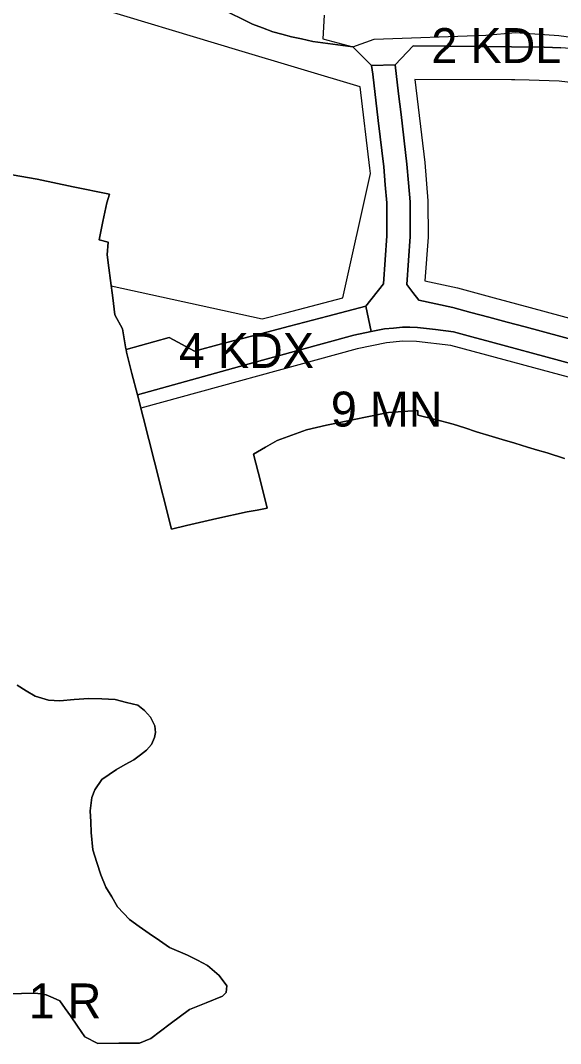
# Model space of a CAD drawing. Extents: x 7422252 to 7424226, y 5538569 to 5540380.
# Drawn here: x 7423241.3 to 7423473.1, y 5539105.5 to 5539544.8 of the extents above; entities that cross this region are included whole.
import ezdxf

# ---------------------------------------------------------------- set-up
doc = ezdxf.new("R2010")
doc.units = 0
for name, color, linetype in [('linie_rozgraniczajace', 7, 'Continuous'), ('linie_zabudowy_nieprzekraczalne', 7, 'Continuous'), ('oznaczenia_przeznaczen', 7, 'Continuous')]:
    doc.layers.add(name, color=color, linetype=linetype)

msp = doc.modelspace()

# ---------------------------------------------------------------- linework, layer by layer
at = {"layer": 'linie_rozgraniczajace'}
for points in [[(7423327.05, 5539549.99), (7423340.85, 5539543.2), (7423345.26, 5539541.53), (7423349.67, 5539539.85), (7423353.43, 5539538.87), (7423357.61, 5539537.79), (7423362, 5539536.8), (7423366.79, 5539535.72), (7423375.39, 5539534.56), (7423383.98, 5539533.39), (7423392.01, 5539525.41), (7423392.53, 5539521.74), (7423394.89, 5539501.82), (7423397.25, 5539481.91), (7423397.88, 5539474.2), (7423398.51, 5539466.5), (7423398.55, 5539459.42), (7423398.6, 5539452.35), (7423397.86, 5539442), (7423397.12, 5539431.65), (7423389.6, 5539422.06), (7423373.16, 5539417.77), (7423356.72, 5539413.47), (7423342.12, 5539409.7), (7423327.53, 5539405.92), (7423316.06, 5539402.76), (7423305.1, 5539408.56), (7423286.64, 5539403.47), (7423286.58, 5539403.78), (7423285.85, 5539408.09), (7423285.11, 5539412.39), (7423281.84, 5539418.31), (7423280.9, 5539425.68), (7423279.95, 5539433.06), (7423279.25, 5539438.59), (7423278.54, 5539444.13), (7423278.91, 5539449.5), (7423275.05, 5539450.54), (7423276.69, 5539458.48), (7423278.33, 5539466.42), (7423279.5, 5539470.1), (7423263.98, 5539473.36), (7423248.47, 5539476.61), (7423237.81, 5539478.49)], [(7423371.61, 5539547.02), (7423371.09, 5539536.9), (7423383.98, 5539533.39), (7423375.39, 5539534.56), (7423366.79, 5539535.72), (7423362, 5539536.8), (7423357.61, 5539537.79), (7423353.43, 5539538.87), (7423349.67, 5539539.85), (7423345.26, 5539541.53), (7423340.85, 5539543.2), (7423327.05, 5539549.99)], [(7423402.14, 5539525.64), (7423409.89, 5539533.83), (7423438.01, 5539533.58), (7423466.12, 5539533.33), (7423473.15, 5539533.05)], [(7423389.6, 5539422.06), (7423397.12, 5539431.65), (7423397.86, 5539442), (7423398.6, 5539452.35), (7423398.55, 5539459.42), (7423398.51, 5539466.5), (7423397.88, 5539474.2), (7423397.25, 5539481.91), (7423394.89, 5539501.82), (7423392.53, 5539521.74), (7423392.01, 5539525.41), (7423402.14, 5539525.64), (7423403.61, 5539513.23), (7423404.66, 5539504.35), (7423407.19, 5539483.06), (7423407.85, 5539475), (7423408.51, 5539466.94), (7423408.55, 5539459.48), (7423408.6, 5539452.02), (7423407.86, 5539441.69), (7423407.12, 5539431.37), (7423409.7, 5539428.01), (7423412.27, 5539424.65), (7423419.55, 5539423.08), (7423426.83, 5539421.5), (7423434.6, 5539419.41), (7423442.37, 5539417.32), (7423450.13, 5539415.23), (7423457.88, 5539413.14), (7423481.67, 5539406.73)], [(7423481.67, 5539406.73), (7423457.88, 5539413.14), (7423450.13, 5539415.23), (7423442.37, 5539417.32), (7423434.6, 5539419.41), (7423426.83, 5539421.5), (7423419.55, 5539423.08), (7423412.27, 5539424.65), (7423409.7, 5539428.01), (7423407.12, 5539431.37), (7423407.86, 5539441.69), (7423408.6, 5539452.02), (7423408.55, 5539459.48), (7423408.51, 5539466.94), (7423407.85, 5539475), (7423407.19, 5539483.06), (7423404.66, 5539504.35), (7423403.61, 5539513.23), (7423402.14, 5539525.64)], [(7423237.81, 5539478.49), (7423248.47, 5539476.61), (7423263.98, 5539473.36), (7423279.5, 5539470.1), (7423278.33, 5539466.42), (7423276.69, 5539458.48), (7423275.05, 5539450.54), (7423278.91, 5539449.5), (7423278.54, 5539444.13), (7423279.25, 5539438.59), (7423279.95, 5539433.06), (7423280.9, 5539425.68), (7423281.84, 5539418.31), (7423285.11, 5539412.39), (7423285.85, 5539408.09), (7423286.58, 5539403.78), (7423286.64, 5539403.47), (7423286.82, 5539402.39), (7423289.15, 5539393.22), (7423291.49, 5539384.06), (7423298.83, 5539355.2), (7423306.18, 5539326.34), (7423312.56, 5539327.92), (7423325.58, 5539330.87), (7423338.59, 5539333.83), (7423342.9, 5539334.56), (7423347.21, 5539335.3), (7423344.3, 5539346.93), (7423341.4, 5539358.56), (7423346.43, 5539361.48), (7423351.45, 5539364.4), (7423357.79, 5539366.71), (7423364.13, 5539369.02), (7423368.42, 5539369.99), (7423372.71, 5539370.95), (7423376.88, 5539371.8), (7423381.04, 5539372.65), (7423389.43, 5539374.36), (7423399.23, 5539376.36), (7423405.4, 5539376.82), (7423411.86, 5539377.31), (7423411.86, 5539375.24), (7423419.47, 5539373.36), (7423427.08, 5539371.47)], [(7423502.3, 5539390.81), (7423472.64, 5539398.81), (7423442.98, 5539406.8), (7423435.05, 5539408.93), (7423427.12, 5539411.07), (7423419.39, 5539412.01), (7423411.66, 5539412.95), (7423408.44, 5539413.03), (7423405.22, 5539413.1), (7423401.37, 5539412.69), (7423397.52, 5539412.29), (7423394.68, 5539411.72), (7423391.84, 5539411.15), (7423389.6, 5539422.06)], [(7423474.83, 5539356.61), (7423467.35, 5539359.07), (7423463.16, 5539360.32), (7423458.98, 5539361.57), (7423453.48, 5539363.22), (7423447.98, 5539364.86), (7423443.78, 5539366.12), (7423436.96, 5539368.16), (7423432.02, 5539369.81), (7423427.08, 5539371.47), (7423419.47, 5539373.36), (7423411.86, 5539375.24), (7423411.86, 5539377.31), (7423405.4, 5539376.82), (7423399.23, 5539376.36), (7423389.43, 5539374.36), (7423381.04, 5539372.65), (7423376.88, 5539371.8), (7423372.71, 5539370.95), (7423368.42, 5539369.99), (7423364.13, 5539369.02), (7423357.79, 5539366.71), (7423351.45, 5539364.4), (7423346.43, 5539361.48), (7423341.4, 5539358.56), (7423344.3, 5539346.93), (7423347.21, 5539335.3), (7423342.9, 5539334.56), (7423338.59, 5539333.83), (7423325.58, 5539330.87), (7423312.56, 5539327.92), (7423306.18, 5539326.34), (7423298.83, 5539355.2), (7423291.49, 5539384.06), (7423337.92, 5539396.85), (7423384.36, 5539409.65), (7423391.84, 5539411.15), (7423394.68, 5539411.72), (7423397.52, 5539412.29), (7423401.37, 5539412.69), (7423405.22, 5539413.1), (7423408.44, 5539413.03), (7423411.66, 5539412.95), (7423419.39, 5539412.01), (7423427.12, 5539411.07), (7423435.05, 5539408.93), (7423442.98, 5539406.8), (7423472.64, 5539398.81), (7423502.3, 5539390.81)], [(7423427.08, 5539371.47), (7423432.02, 5539369.81), (7423436.96, 5539368.16), (7423443.78, 5539366.12), (7423447.98, 5539364.86), (7423453.48, 5539363.22), (7423458.98, 5539361.57), (7423463.16, 5539360.32), (7423467.35, 5539359.07), (7423474.83, 5539356.61)], [(7423239.86, 5539259.34), (7423243.77, 5539256.98), (7423247.69, 5539254.62), (7423250.56, 5539253.75), (7423253.43, 5539252.89), (7423255.8, 5539252.8), (7423258.18, 5539252.7), (7423264.42, 5539253.19), (7423270.66, 5539253.68), (7423276.31, 5539253.42), (7423281.96, 5539253.16), (7423286.81, 5539251.97), (7423291.67, 5539250.78), (7423294.59, 5539248.47), (7423297.09, 5539245.58), (7423297.77, 5539244.44), (7423299, 5539241.83), (7423299.21, 5539238.97), (7423298.89, 5539236.94), (7423297.53, 5539233.93), (7423295.38, 5539231.43), (7423292.83, 5539229.39), (7423289.92, 5539227.29), (7423286.23, 5539225.23), (7423282.55, 5539223.18), (7423276.28, 5539218.84), (7423273.2, 5539214.47), (7423271.95, 5539211.09), (7423271.28, 5539205.34), (7423271.47, 5539200.71), (7423271.66, 5539196.08), (7423272.44, 5539188.6), (7423274.15, 5539183.27), (7423275.86, 5539177.94), (7423277.96, 5539172.64), (7423280.5, 5539168.42), (7423283.04, 5539164.21), (7423285.56, 5539161.45), (7423288.08, 5539158.68), (7423292.33, 5539155.73), (7423296.58, 5539152.77), (7423300.96, 5539149.77), (7423305.35, 5539146.77), (7423312.98, 5539143.38), (7423317.29, 5539141.22), (7423321.6, 5539139.06), (7423326.67, 5539134.73), (7423329.86, 5539130.23), (7423329.6, 5539127.45), (7423328.01, 5539125.86), (7423320.98, 5539122.99), (7423313.94, 5539120.12), (7423305.64, 5539113.91), (7423297.33, 5539107.69), (7423292.42, 5539105.71), (7423283.49, 5539105.6), (7423274.56, 5539105.49), (7423268.9, 5539108.4), (7423265.83, 5539112.88), (7423262.76, 5539117.37), (7423260.48, 5539120.57), (7423258.2, 5539123.77), (7423255.31, 5539125.07), (7423252.42, 5539126.37), (7423250, 5539126.76), (7423247.59, 5539127.15), (7423241.8, 5539127.02), (7423236.02, 5539126.88)], [(7423271.95, 5539211.09), (7423273.2, 5539214.47), (7423276.28, 5539218.84), (7423282.55, 5539223.18), (7423286.23, 5539225.23), (7423289.92, 5539227.29), (7423292.83, 5539229.39), (7423295.38, 5539231.43), (7423297.53, 5539233.93), (7423298.89, 5539236.94), (7423299.21, 5539238.97), (7423299, 5539241.83), (7423297.77, 5539244.44), (7423297.09, 5539245.58), (7423294.59, 5539248.47), (7423291.67, 5539250.78), (7423286.81, 5539251.97), (7423281.96, 5539253.16), (7423276.31, 5539253.42), (7423270.66, 5539253.68), (7423264.42, 5539253.19), (7423258.18, 5539252.7), (7423255.8, 5539252.8), (7423253.43, 5539252.89), (7423250.56, 5539253.75), (7423247.69, 5539254.62), (7423243.77, 5539256.98), (7423239.86, 5539259.34)], [(7423236.02, 5539126.88), (7423241.8, 5539127.02), (7423247.59, 5539127.15), (7423250, 5539126.76), (7423252.42, 5539126.37), (7423255.31, 5539125.07), (7423258.2, 5539123.77), (7423260.48, 5539120.57), (7423262.76, 5539117.37), (7423265.83, 5539112.88), (7423268.9, 5539108.4), (7423274.56, 5539105.49), (7423283.49, 5539105.6), (7423292.42, 5539105.71), (7423297.33, 5539107.69), (7423305.64, 5539113.91), (7423313.94, 5539120.12), (7423320.98, 5539122.99), (7423328.01, 5539125.86), (7423329.6, 5539127.45), (7423329.86, 5539130.23), (7423326.67, 5539134.73), (7423321.6, 5539139.06), (7423317.29, 5539141.22), (7423312.98, 5539143.38), (7423305.35, 5539146.77), (7423300.96, 5539149.77), (7423296.58, 5539152.77), (7423292.33, 5539155.73), (7423288.08, 5539158.68), (7423285.56, 5539161.45), (7423283.04, 5539164.21), (7423280.5, 5539168.42), (7423277.96, 5539172.64), (7423275.86, 5539177.94), (7423274.15, 5539183.27), (7423272.44, 5539188.6), (7423271.66, 5539196.08), (7423271.47, 5539200.71), (7423271.28, 5539205.34), (7423271.95, 5539211.09)]]:
    msp.add_lwpolyline(points, dxfattribs=at)
for points in [[(7423383.98, 5539533.39), (7423393.18, 5539536.72), (7423441.09, 5539538.46), (7423453.71, 5539539.65), (7423472.39, 5539538.27), (7423491.26, 5539535.75), (7423504.79, 5539532.3), (7423528.83, 5539525.52), (7423509.19, 5539528.69), (7423489.54, 5539531.86), (7423481.35, 5539532.46), (7423473.15, 5539533.05), (7423466.12, 5539533.33), (7423438.01, 5539533.58), (7423409.89, 5539533.83), (7423402.14, 5539525.64), (7423392.01, 5539525.41)], [(7423286.64, 5539403.47), (7423305.1, 5539408.56), (7423316.06, 5539402.76), (7423327.53, 5539405.92), (7423342.12, 5539409.7), (7423356.72, 5539413.47), (7423373.16, 5539417.77), (7423389.6, 5539422.06), (7423391.84, 5539411.15), (7423384.36, 5539409.65), (7423337.92, 5539396.85), (7423291.49, 5539384.06), (7423289.15, 5539393.22), (7423286.82, 5539402.39)]]:
    msp.add_lwpolyline(points, close=True, dxfattribs=at)
at = {"layer": 'linie_zabudowy_nieprzekraczalne'}
for points in [[(7423280.23, 5539430.85), (7423345.02, 5539416.64), (7423355.21, 5539419.28), (7423379.73, 5539425.61), (7423391.47, 5539478.99), (7423391.28, 5539481.31), (7423387.15, 5539516.25), (7423335.11, 5539531.92), (7423267.72, 5539552.22)], [(7423410.61, 5539519.38), (7423414.83, 5539483.83), (7423416.18, 5539467.27), (7423416.27, 5539451.77), (7423414.92, 5539432.9), (7423428.87, 5539429.89), (7423444.61, 5539425.64), (7423460.12, 5539421.46), (7423508.16, 5539408.52)], [(7423500.91, 5539515.27), (7423472.54, 5539518.68), (7423472.54, 5539518.68), (7423459.6, 5539519.1), (7423453.41, 5539519.32), (7423452.04, 5539519.31), (7423410.61, 5539519.38)], [(7423514.71, 5539378.45), (7423514.58, 5539378.52), (7423507.12, 5539382.46), (7423500.42, 5539385.11), (7423441.42, 5539401), (7423425.97, 5539405.17), (7423411.23, 5539406.96), (7423405.47, 5539407.09), (7423398.43, 5539406.35), (7423385.75, 5539403.81), (7423292.97, 5539378.24)]]:
    msp.add_lwpolyline(points, dxfattribs=at)

# ---------------------------------------------------------------- texts
at = {"layer": 'oznaczenia_przeznaczen'}
for s, p in [('2 KDL', (7423417.66, 5539526.47)), ('4 KDX', (7423309.3, 5539395.58)), ('9 MN', (7423374.52, 5539370.39)), ('1 R', (7423244.84, 5539116.27))]:
    msp.add_text(s, height=15, dxfattribs=at).set_placement(p)

doc.saveas('drawing.dxf')
